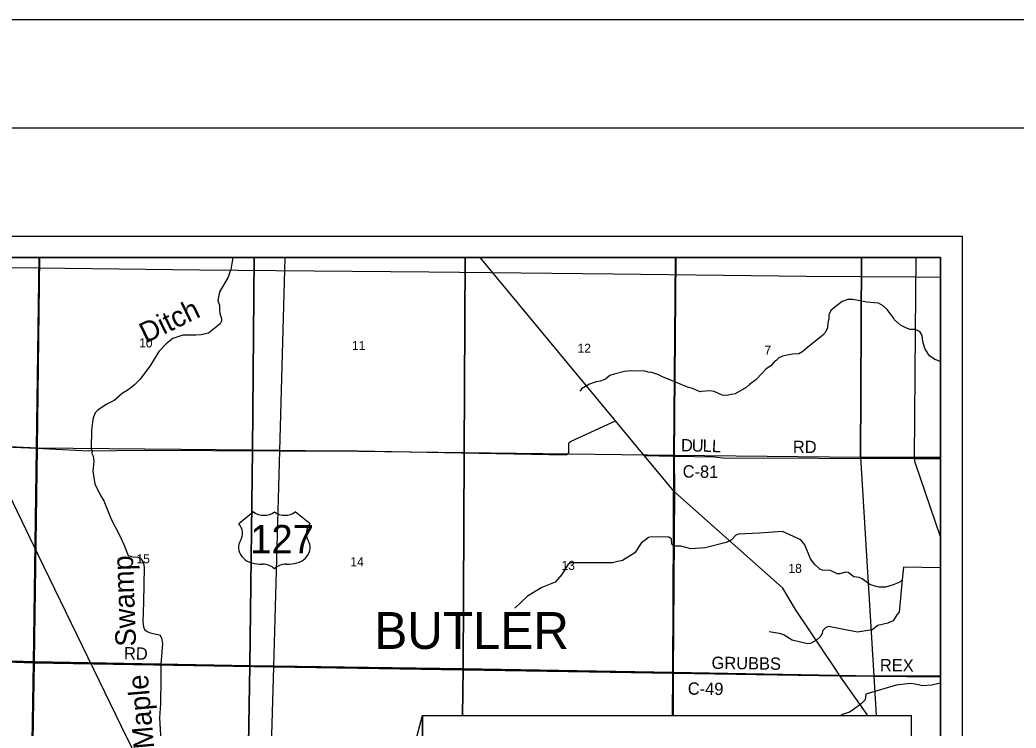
# Model space of a CAD drawing. Extents: x 0 to 1391, y -24 to 440.
# Drawn here: x 242.9 to 335, y 374.5 to 440 of the extents above; entities that cross this region are included whole.
import ezdxf

# ---------------------------------------------------------------- set-up
doc = ezdxf.new("R2010")
doc.units = 0
for name, color, linetype in [('GM_X_Corporation', 7, 'Continuous'), ('GM_X_County_Road', 7, 'Continuous'), ('GM_X_County_Road_Text', 7, 'Continuous'), ('GM_X_Minor_River', 7, 'Continuous'), ('GM_X_Minor_River_Text', 7, 'Continuous'), ('GM_X_Rail_Line', 7, 'Continuous'), ('GM_X_Section_Text', 7, 'Continuous'), ('GM_X_State_Route', 7, 'Continuous'), ('GM_X_Township_Road', 7, 'Continuous'), ('GM_X_Township_Road_Text', 7, 'Continuous'), ('GM_X_Township_Text', 7, 'Continuous'), ('GM_X_US_Route', 7, 'Continuous'), ('GM_X_US_Shield', 7, 'Continuous'), ('SH_Border', 7, 'Continuous'), ('SH_Cut_Line', 7, 'Continuous'), ('SH_Data', 7, 'Continuous'), ('SH_Text', 7, 'Continuous')]:
    doc.layers.add(name, color=color, linetype=linetype)

msp = doc.modelspace()

# ---------------------------------------------------------------- linework, layer by layer
at = {"layer": 'GM_X_Corporation'}
for points in [[(328, 319.315), (328, 418), (192, 418), (192, 321.564), (192.576, 321.541), (192.664, 321.541), (192.727, 321.547), (192.779, 321.557), (192.829, 321.575), (220.578, 320.983), (223.103, 320.888), (242.96, 320.5), (270.99, 319.899), (282.746, 319.815)], [(303.268, 375.642), (303.268, 379.55), (303.387, 396.347), (303.371, 399.65), (303.511, 418), (192, 418), (192, 321.564), (192.576, 321.541), (192.664, 321.541), (192.727, 321.547), (192.779, 321.557), (192.829, 321.575), (220.578, 320.983), (223.103, 320.888), (242.96, 320.5), (270.99, 319.899), (282.746, 319.815), (282.759, 319.815), (302.742, 319.575), (302.926, 339.542), (302.977, 347.773), (303.13, 359.466), (303.222, 366.207)], [(303.222, 366.207), (303.13, 359.466), (302.977, 347.773), (302.926, 339.542), (302.742, 319.575), (320.232, 319.401), (320.28, 319.374), (320.324, 319.361), (320.375, 319.355), (320.47, 319.355), (321.557, 319.363), (321.681, 319.364), (322.004, 319.36), (323.626, 319.346), (324.492, 319.344), (326.017, 319.331), (327.358, 319.321), (328, 319.315), (328, 418), (303.511, 418), (303.371, 399.65), (303.387, 396.347), (303.268, 379.55), (303.268, 375.642)], [(283.626, 366.207), (283.516, 359.849), (263.777, 360.241), (264.126, 380.236), (283.862, 379.958), (283.788, 375.642)], [(283.788, 375.642), (283.862, 379.958), (303.251, 379.605), (303.219, 375.642)], [(303.219, 375.642), (303.251, 379.605), (321.821, 379.279), (322.048, 375.642)], [(322.635, 366.207), (323.057, 359.423), (328, 359.363), (328, 379.272), (321.821, 379.279), (322.048, 375.642)]]:
    msp.add_lwpolyline(points, dxfattribs=at)
for points in [[(244.682, 418), (224.862, 418), (224.571, 401.359), (244.46, 400.407)], [(264.526, 418), (244.682, 418), (244.46, 400.407), (264.377, 400.226)], [(284.043, 418), (264.526, 418), (264.377, 400.226), (283.949, 399.966)], [(303.502, 418), (284.043, 418), (283.949, 399.966), (303.333, 399.728)], [(320.692, 418), (303.502, 418), (303.333, 399.728), (320.595, 399.529)], [(328, 399.5), (328, 418), (320.692, 418), (320.595, 399.529)], [(224.571, 401.359), (244.46, 400.407), (244.192, 380.606), (224.18, 381.198)], [(244.46, 400.407), (264.377, 400.226), (264.126, 380.236), (244.192, 380.606)], [(264.377, 400.226), (283.949, 399.966), (283.862, 379.958), (264.126, 380.236)], [(303.333, 399.728), (303.251, 379.605), (283.862, 379.958), (283.949, 399.966)], [(320.595, 399.529), (321.821, 379.279), (303.251, 379.605), (303.333, 399.728)], [(328, 379.272), (328, 399.5), (320.595, 399.529), (321.821, 379.279)], [(224.18, 381.198), (244.192, 380.606), (243.843, 360.611), (223.71, 361.213)], [(244.192, 380.606), (264.126, 380.236), (263.777, 360.241), (243.843, 360.611)]]:
    msp.add_lwpolyline(points, close=True, dxfattribs=at)
at = {"layer": 'GM_X_County_Road'}
for points in [[(224.518, 401.352), (228.286, 401.123), (233.443, 400.81), (240.013, 400.55), (244.384, 400.368), (249.197, 400.127), (254.378, 400.182), (266.897, 400.139), (274.089, 400.133), (293.389, 399.761), (293.534, 399.82), (293.612, 399.955), (293.635, 400.797), (293.667, 400.902), (293.828, 401.013), (297.937, 402.911)], [(300.606, 399.695), (303.375, 399.64), (303.415, 399.639)], [(303.415, 399.639), (307.078, 399.566), (307.864, 399.491), (325.606, 399.425), (328, 399.417)], [(303.246, 375.642), (303.273, 379.539), (303.392, 396.336)], [(303.273, 379.539), (318.688, 379.317), (328, 379.216)]]:
    msp.add_lwpolyline(points, dxfattribs=at)
at = {"layer": 'GM_X_Minor_River'}
for points in [[(262.553, 418), (262.369, 416.903), (262.091, 416.143), (261.313, 414.85), (261.169, 414.018), (261.31, 413.619), (261.322, 413.208), (261.357, 412.827), (261.519, 412.383), (261.52, 412.117), (261.377, 411.885), (260.292, 411.025), (259.597, 410.861), (259.141, 410.836), (258.928, 410.826), (257.935, 410.838), (257.015, 410.52), (256.388, 410.036), (255.709, 409.325), (254.906, 407.979), (253.962, 406.72), (253.47, 406.224), (252.959, 405.82), (252.326, 405.427), (251.565, 404.778), (250.842, 404.426), (250.069, 403.899), (249.835, 403.647), (249.665, 403.234), (249.613, 403.015), (249.495, 402.023), (249.458, 400.337), (249.535, 400.1), (249.521, 399.887), (249.628, 399.626), (249.714, 399.168), (249.622, 398.251), (249.787, 397.069), (250.291, 396.052), (250.633, 395.511), (251.3, 393.814), (252.064, 392.312), (252.474, 391.465), (252.863, 390.444), (253.308, 390.311), (253.769, 390.275), (254.054, 390.146), (254.237, 389.891), (254.3, 389.691), (254.352, 389.371), (254.28, 386.128), (254.246, 384.328), (254.301, 383.832), (254.393, 383.579), (254.623, 383.398), (254.909, 383.284), (255.633, 383.135), (255.828, 383.054), (255.972, 382.777), (256.035, 382.289), (255.908, 380.392), (255.908, 379.267), (255.902, 379.047), (255.854, 376.714), (255.765, 375.409), (255.985, 371.746)], [(328, 408.374), (327.751, 408.479), (327.468, 408.583), (326.976, 408.916), (326.584, 409.518), (326.498, 409.81), (326.349, 410.242), (326.294, 410.784), (326.098, 411.172), (325.905, 411.234), (325.808, 411.276), (325.637, 411.344), (325.185, 411.364), (324.791, 411.51), (324.31, 411.744), (323.741, 412.247), (323.605, 412.451), (323.076, 413.195), (322.682, 413.539), (322.277, 413.785), (321.186, 413.885), (319.898, 414.116), (319.438, 414.128), (318.91, 413.93), (318.101, 413.327), (318.054, 413.269), (317.882, 413.132), (317.679, 412.745), (317.665, 412.381), (317.566, 411.968), (317.533, 411.521), (317.351, 411.118), (317.129, 410.832), (315.696, 409.678), (315.267, 409.317), (314.889, 409.113), (314.321, 409.07), (313.379, 408.882), (313.041, 408.73), (312.79, 408.498), (312.72, 408.44), (312.303, 407.987), (311.876, 407.701), (311.523, 407.352), (310.909, 406.703), (310.349, 406.263), (310.014, 405.989), (308.995, 405.388), (308.66, 405.326), (308.204, 405.247), (307.798, 405.265), (307.072, 405.623), (306.675, 405.678), (305.887, 405.606), (305.765, 405.588), (305.068, 405.892), (304.598, 406.026), (304.546, 406.051), (303.641, 406.432), (302.281, 406.978), (301.852, 407.194), (301.316, 407.369), (300.948, 407.415), (300.641, 407.489), (299.382, 407.521), (298.769, 407.456)], [(298.769, 407.456), (297.824, 407.216), (297.427, 407.096), (297.006, 406.765), (296.546, 406.573), (296.144, 406.499), (296.052, 406.465), (295.539, 406.282), (294.798, 405.858), (294.71, 405.717), (294.639, 405.645)], [(328, 389.308), (324.588, 389.364), (324.446, 388.197), (324.23, 387.981), (323.619, 387.711), (322.926, 387.504), (322.29, 387.523), (322.04, 387.558), (321.461, 387.766), (320.75, 388.288), (320.471, 388.392), (319.972, 388.454), (319.472, 388.873), (319.223, 388.901), (318.682, 388.743), (318.439, 388.756), (317.831, 389.063), (317.096, 389.084), (316.841, 389.187), (316.37, 389.598), (315.986, 390.137), (315.44, 391.422), (315.085, 391.892), (313.371, 392.659), (311.216, 392.494), (309.32, 392.422), (309.06, 392.313), (308.659, 391.88), (308.185, 391.63), (306.244, 391.164), (304.916, 391.044), (303.995, 391.289), (303.329, 391.308), (303.166, 391.501), (303.129, 391.995), (302.881, 392.144), (301.268, 392.166), (301.001, 392.102), (300.325, 391.591), (299.741, 390.675), (298.584, 389.983), (297.877, 389.821), (297.664, 389.764), (293.829, 389.75), (293.562, 389.641), (292.984, 388.68), (292.358, 387.977), (291.144, 387.483), (289.804, 386.68), (288.64, 385.578)], [(324.446, 388.197), (324.181, 385.187), (323.949, 384.941), (323.613, 384.393), (323.132, 384.174), (322.204, 383.956), (321.666, 383.571), (320.329, 383.352), (317.648, 383.865), (317.373, 383.733), (317.104, 383.51), (317.069, 383.26), (316.92, 382.982), (316.534, 382.609), (315.983, 382.301), (315.687, 382.26), (314.284, 382.598), (313.542, 383.067), (313.248, 383.186), (312.153, 383.373)], [(328, 378.626), (327.837, 378.602), (327.197, 378.432), (326.363, 378.387), (325.661, 378.529), (325.192, 378.606), (323.886, 378.456), (321.083, 377.619), (321.028, 377.073), (320.657, 376.7), (319.843, 376.084), (319.59, 375.93), (318.829, 375.701), (318.766, 375.642)]]:
    msp.add_lwpolyline(points, dxfattribs=at)
at = {"layer": 'GM_X_Rail_Line'}
for points in [[(234.745, 417.15), (239.522, 417.117), (259.458, 416.885), (280.674, 416.7), (297.717, 416.49), (315.614, 416.28), (325.691, 416.226), (328, 416.195)], [(238.027, 404.003), (244.526, 390.518), (252.745, 373.576), (253.82, 371.455), (254.704, 369.774), (255.571, 368.177), (256.476, 366.691), (257.419, 365.224), (262.101, 357.987), (269.815, 345.966), (270.674, 344.606), (271.192, 343.55), (271.576, 342.434), (271.787, 341.356), (271.88, 340.154), (271.887, 336.624), (271.911, 335.453), (272.116, 334.347), (272.385, 332.985), (272.717, 331.486), (272.974, 330.255), (273.021, 329.336), (272.865, 320.047)]]:
    msp.add_lwpolyline(points, dxfattribs=at)
at = {"layer": 'GM_X_State_Route'}
for points in [[(303.392, 396.336), (300.606, 399.695), (297.937, 402.911), (285.416, 418)], [(318.242, 379.984), (314.579, 385.456), (313.417, 387.42), (303.392, 396.336)], [(321.287, 375.642), (318.688, 379.317), (318.242, 379.984)]]:
    msp.add_lwpolyline(points, dxfattribs=at)
at = {"layer": 'GM_X_Township_Road'}
for p, q in [((244.384, 400.368), (244.65, 418)), ((325.693, 411.148), (325.743, 418)), ((325.606, 399.425), (325.693, 411.148)), ((224.11, 381.123), (244.121, 380.516)), ((244.121, 380.516), (266.353, 380.126)), ((266.353, 380.126), (303.273, 379.539))]:
    msp.add_line(p, q, dxfattribs=at)
for points in [[(242.964, 320.489), (243.094, 330.463), (243.304, 340.47), (243.777, 360.525), (244.121, 380.516), (244.384, 400.368)], [(328, 392.172), (325.668, 399.06), (325.606, 399.425)]]:
    msp.add_lwpolyline(points, dxfattribs=at)
at = {"layer": 'GM_X_US_Route'}
msp.add_lwpolyline([(265.729, 359.525), (265.729, 359.545), (265.747, 360.123), (266.353, 380.126), (266.897, 400.139), (267.381, 418)], dxfattribs=at)
at = {"layer": 'GM_X_US_Shield'}
for p, q in [((264.477, 394.477), (263.104, 393.379)), ((269.695, 393.379), (268.322, 394.477)), ((265.026, 389.643), (265.301, 389.643)), ((267.498, 389.643), (267.773, 389.643))]:
    msp.add_line(p, q, dxfattribs=at)
for centre, major_axis, start_param, end_param in [((265.438, 395.262), (-1.373, 0), 0.795399, 2.346194), ((267.361, 395.262), (-1.373, 0), 0.795399, 2.346194), ((261.529, 392.496), (1.923, 0), 5.838949, 6.894067), ((271.27, 392.496), (-1.923, 0), 5.672304, 6.727422), ((265.005, 391.181), (1.923, 0), 2.702327, 4.723529), ((267.794, 391.181), (-1.923, 0), 1.559657, 3.580859), ((265.301, 388.545), (-1.373, 0), 3.785094, 4.712389), ((267.498, 388.545), (-1.373, 0), 4.712389, 5.639684)]:
    msp.add_ellipse(centre, major_axis=major_axis, ratio=0.8, start_param=start_param, end_param=end_param, dxfattribs=at)
at = {"layer": 'SH_Border'}
msp.add_lwpolyline([(30, 430), (670, 430), (670, 10), (30, 10)], close=True, dxfattribs=at)
at = {"layer": 'SH_Cut_Line'}
msp.add_lwpolyline([(0, 0), (680, 0), (680, 440), (0, 440)], close=True, dxfattribs=at)
at = {"layer": 'SH_Data'}
for p, q in [((190, 420), (330, 420)), ((190, 420), (330, 420)), ((330, 420), (330, 280)), ((330, 420), (330, 280)), ((192, 418), (328, 418)), ((328, 418), (328, 282))]:
    msp.add_line(p, q, dxfattribs=at)
at = {"layer": 'SH_Text'}
for points in [[(272.588, 347.5), (280.096, 375.642), (280.096, 366.207)], [(280.096, 375.642), (325.272, 375.642), (325.272, 366.207), (280.096, 366.207)]]:
    msp.add_lwpolyline(points, close=True, dxfattribs=at)

# ---------------------------------------------------------------- texts
at = {"layer": 'GM_X_County_Road_Text'}
for s, height, rotation, p in [('D', 1.136, 358.76501, (303.989, 400.086)), ('U', 1.136, 358.76661, (304.989, 400.064)), ('L', 1.136, 358.48701, (305.987, 400.043)), ('L', 1.136, 356.65531, (306.827, 400.021)), ('RD', 1.1364, 0.00001, (314.346, 399.919)), ('C-81', 1.1364, 358.97011, (304.144, 397.664)), ('GRUBBS', 1.1364, 359.13958, (306.819, 379.953)), ('REX', 1.1364, 359.31423, (322.385, 379.736)), ('C-49', 1.1364, 359.31423, (304.622, 377.564))]:
    msp.add_text(s, height=height, rotation=rotation, dxfattribs=at).set_placement(p)
at = {"layer": 'GM_X_Minor_River_Text'}
for s, height, rotation, p in [('Ditch', 1.8937, 26.0013, (254.501, 410.048)), ('Swamp', 1.8932, 92.00845, (253.609, 382.046)), ('Maple', 1.894, 95.00028, (255.284, 372.62))]:
    msp.add_text(s, height=height, rotation=rotation, dxfattribs=at).set_placement(p)
at = {"layer": 'GM_X_Section_Text'}
for s, height, p in [('10', 0.8371, (253.888, 409.69)), ('11', 0.8371, (273.571, 409.456)), ('12', 0.8371, (294.429, 409.196)), ('7', 0.837, (311.713, 409.017)), ('15', 0.8371, (253.638, 389.717)), ('14', 0.8371, (273.421, 389.446)), ('13', 0.8371, (292.946, 389.106)), ('18', 0.8371, (313.929, 388.831))]:
    msp.add_text(s, height=height, rotation=0.00001, dxfattribs=at).set_placement(p)
at = {"layer": 'GM_X_Township_Road_Text'}
msp.add_text('RD', height=1.1364, rotation=358.51936, dxfattribs=at).set_placement((252.474, 380.836))
at = {"layer": 'GM_X_Township_Text'}
msp.add_text('BUTLER', height=3.4091, rotation=0.00001, dxfattribs=at).set_placement((275.648, 381.795))
at = {"layer": 'GM_X_US_Shield'}
msp.add_text('127', height=2.6367, dxfattribs=at).set_placement((264.162, 390.632))

doc.saveas('drawing.dxf')
